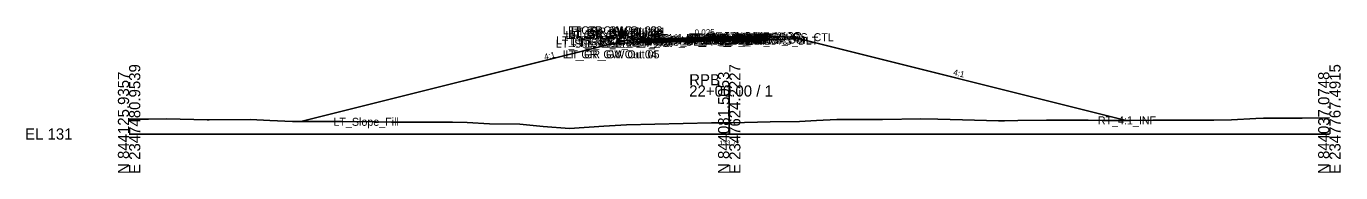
# Model space of a CAD drawing. Extents: x -76 to 2347760, y -10 to 844216.
# Drawn here: x -75.7 to 252.8, y 6990.3 to 7027 of the extents above; entities that cross this region are included whole.
import ezdxf

# ---------------------------------------------------------------- set-up
doc = ezdxf.new("R2010")
doc.units = 0
for name, color, linetype in [('Default', 7, 'Continuous'), ('Exist Cross Section Cell', 7, 'Continuous'), ('Exist XS Center Line Elevation Label', 7, 'Continuous'), ('Exist XS Ground Line', 7, 'Continuous'), ('Prop CMT Pvmt Course 1', 7, 'Continuous'), ('Prop CMT Pvmt Course 2', 7, 'Continuous'), ('Prop CMT Pvmt Course 3', 7, 'Continuous'), ('Prop CMT Pvmt Surface', 7, 'Continuous'), ('Prop CMT Pvmt Surface Shoulder', 7, 'Continuous'), ('Prop CMT Shld Paved Course 1', 7, 'Continuous'), ('Prop CMT Shld Paved Course 2', 7, 'Continuous'), ('Prop CMT Shld Paved Course 3', 7, 'Continuous'), ('Prop CMT Slope Grass', 7, 'Continuous'), ('Prop CMT Subgrade Earthwork', 7, 'Continuous'), ('Prop XS Earthwork Shape', 7, 'Continuous'), ('Prop XS SE Text', 7, 'Continuous'), ('Prop XS Side Slope Text', 7, 'Continuous'), ('Scratch_Level_0', 7, 'Continuous')]:
    doc.layers.add(name, color=color, linetype=linetype)

msp = doc.modelspace()

# ---------------------------------------------------------------- linework, layer by layer
at = {"layer": 'Exist Cross Section Cell'}
for p, q in [((100, 7000), (100, 7012.17)), ((-50, 7000), (100, 7000)), ((100, 7000), (250, 7000))]:
    msp.add_line(p, q, dxfattribs=at)
at = {"layer": 'Exist XS Ground Line'}
msp.add_lwpolyline([(-50, 7003.75), (-45.15, 7003.71), (-40.59, 7003.79), (-30.46, 7003.57), (-29.97, 7003.57), (-19.65, 7003.59), (-14.79, 7003.41), (-9.18, 7003.16), (0.38, 7003.16), (1.29, 7003.15), (3.3, 7003.13), (11.76, 7003.04), (15.56, 7002.99), (19.85, 7002.94), (30.86, 7002.99), (34.5, 7002.88), (40.1, 7002.57), (47.65, 7002.48), (53.53, 7001.9), (60.11, 7001.34), (68.66, 7001.95), (74.34, 7002.33), (95.59, 7002.83), (100, 7002.77), (100.64, 7002.78), (110.23, 7003.03), (117.55, 7003.16), (121.8, 7003.42), (126.93, 7003.6), (136.98, 7003.63), (137.4, 7003.61), (138.35, 7003.63), (147.87, 7003.81), (152.15, 7003.71), (158.34, 7003.53), (167.33, 7003.33), (168.81, 7003.33), (172.11, 7003.38), (179.28, 7003.5), (182.51, 7003.5), (189.75, 7003.46), (193.57, 7003.41), (200.22, 7003.42), (205.87, 7003.46), (210.69, 7003.47), (217.54, 7003.49), (221.16, 7003.48), (225.53, 7003.54), (231.63, 7003.86), (233.53, 7003.99), (239.63, 7003.98), (242.1, 7004), (243.21, 7003.99), (250, 7004.06)], dxfattribs=at)
at = {"layer": 'Prop CMT Pvmt Course 1'}
for p, q in [((100, 7024.31), (88, 7024.01)), ((88, 7023.76), (100, 7024.06)), ((100, 7024.31), (104, 7024.41)), ((100, 7024.06), (100, 7024.31)), ((100, 7024.06), (100, 7024.31)), ((100, 7024.06), (100, 7024.18)), ((100, 7024.18), (100, 7024.18)), ((100, 7024.18), (100, 7024.06)), ((100, 7024.06), (100, 7024.18)), ((100, 7024.18), (100, 7024.18)), ((100, 7024.18), (100, 7024.06)), ((104, 7024.16), (100, 7024.06)), ((100, 7024.06), (100, 7024.06)), ((100, 7024.06), (100, 7024.06)), ((104, 7024.41), (104, 7024.16)), ((88, 7024.01), (88, 7023.76))]:
    msp.add_line(p, q, dxfattribs=at)
at = {"layer": 'Prop CMT Pvmt Course 2'}
for p, q in [((100, 7024.06), (88, 7023.76)), ((100, 7024.06), (104, 7024.16)), ((100, 7023.72), (100, 7024.06)), ((100, 7023.72), (100, 7024.06)), ((104, 7024.16), (104, 7023.82)), ((88, 7023.76), (88, 7023.42)), ((88, 7023.42), (100, 7023.72)), ((104, 7023.82), (100, 7023.72))]:
    msp.add_line(p, q, dxfattribs=at)
at = {"layer": 'Prop CMT Pvmt Course 3'}
for p, q in [((100, 7023.72), (88, 7023.42)), ((88, 7023.42), (88, 7023.09)), ((88, 7023.09), (100, 7023.39)), ((100, 7023.72), (104, 7023.82)), ((100, 7023.39), (100, 7023.72)), ((100, 7023.39), (100, 7023.72)), ((104, 7023.49), (100, 7023.39)), ((104, 7023.82), (104, 7023.49))]:
    msp.add_line(p, q, dxfattribs=at)
at = {"layer": 'Prop CMT Pvmt Surface'}
for q in [(88, 7024.01), (104, 7024.41)]:
    msp.add_line((100, 7024.31), q, dxfattribs=at)
at = {"layer": 'Prop CMT Pvmt Surface Shoulder'}
for p, q in [((104, 7024.41), (108, 7024.51)), ((88, 7024.01), (78, 7023.76))]:
    msp.add_line(p, q, dxfattribs=at)
at = {"layer": 'Prop CMT Shld Paved Course 1'}
for p, q in [((104, 7024.41), (108, 7024.51)), ((104, 7024.16), (104, 7024.41)), ((108.24, 7024.26), (104, 7024.16)), ((108, 7024.51), (108.24, 7024.26)), ((78, 7023.76), (77.74, 7023.5)), ((77.74, 7023.5), (88, 7023.76)), ((88, 7024.01), (78, 7023.76)), ((88, 7023.76), (88, 7024.01))]:
    msp.add_line(p, q, dxfattribs=at)
at = {"layer": 'Prop CMT Shld Paved Course 2'}
for p, q in [((104, 7024.16), (108.24, 7024.26)), ((104, 7023.82), (104, 7024.16)), ((108.24, 7024.26), (108.57, 7023.94)), ((77.74, 7023.5), (77.4, 7023.16)), ((77.4, 7023.16), (88, 7023.42)), ((88, 7023.76), (77.74, 7023.5)), ((88, 7023.42), (88, 7023.76)), ((108.57, 7023.94), (104, 7023.82))]:
    msp.add_line(p, q, dxfattribs=at)
at = {"layer": 'Prop CMT Shld Paved Course 3'}
for p, q in [((76.9, 7023.15), (76.56, 7022.8)), ((76.56, 7022.8), (88, 7023.09)), ((77.4, 7023.16), (76.9, 7023.15)), ((88, 7023.42), (77.4, 7023.16)), ((88, 7023.09), (88, 7023.42)), ((104, 7023.82), (108.57, 7023.94)), ((104, 7023.49), (104, 7023.82)), ((109.39, 7023.62), (104, 7023.49)), ((108.57, 7023.94), (109.07, 7023.95)), ((109.07, 7023.95), (109.39, 7023.62))]:
    msp.add_line(p, q, dxfattribs=at)
at = {"layer": 'Prop CMT Slope Grass'}
for p, q in [((108, 7024.51), (116, 7024.23)), ((116, 7024.23), (199.25, 7003.41)), ((74, 7023.44), (-7.1, 7003.16)), ((78, 7023.76), (74, 7023.44))]:
    msp.add_line(p, q, dxfattribs=at)
at = {"layer": 'Prop CMT Subgrade Earthwork'}
for p, q in [((76.56, 7022.8), (70.9, 7022.66)), ((88, 7023.09), (76.56, 7022.8)), ((100, 7023.39), (88, 7023.09)), ((100, 7023.39), (104, 7023.49)), ((104, 7023.49), (117.59, 7023.83))]:
    msp.add_line(p, q, dxfattribs=at)
at = {"layer": 'Prop XS Earthwork Shape'}
msp.add_lwpolyline([(182.51, 7003.5), (189.75, 7003.46), (193.57, 7003.41), (199.25, 7003.41), (117.59, 7023.83), (104, 7023.49), (100, 7023.39), (88, 7023.09), (76.56, 7022.8), (70.9, 7022.66), (-7.1, 7003.16), (0.38, 7003.16), (1.29, 7003.15), (3.3, 7003.13), (11.76, 7003.04), (15.56, 7002.99), (19.85, 7002.94), (30.86, 7002.99), (34.5, 7002.88), (40.1, 7002.57), (47.65, 7002.48), (53.53, 7001.9), (60.11, 7001.34), (68.66, 7001.95), (74.34, 7002.33), (95.59, 7002.83), (100, 7002.77), (100.64, 7002.78), (110.23, 7003.03), (117.55, 7003.16), (121.8, 7003.42), (126.93, 7003.6), (136.98, 7003.63), (137.4, 7003.61), (138.35, 7003.63), (147.87, 7003.81), (152.15, 7003.71), (158.34, 7003.53), (167.33, 7003.33), (168.81, 7003.33), (172.11, 7003.38), (179.28, 7003.5)], close=True, dxfattribs=at)

# ---------------------------------------------------------------- texts
at = {"layer": 'Default'}
msp.add_text('-', height=0.0001, dxfattribs=at).set_placement((-50, 7000))
at = {"layer": 'Exist Cross Section Cell'}
for s, p in [('N 844125.9357', (-50, 6990)), ('E 2347480.9539', (-47.2, 6990)), ('N 844081.5053', (100, 6990)), ('E 2347624.2227', (102.8, 6990)), ('N 844037.0748', (250, 6990)), ('E 2347767.4915', (252.8, 6990))]:
    msp.add_text(s, height=2.8, rotation=90, dxfattribs=at).set_placement(p)
for s, p in [('RPB', (90, 7012.17)), ('22+00.00 / 1', (90, 7009.37)), ('EL 131', (-76, 6998.6))]:
    msp.add_text(s, height=2.8, dxfattribs=at).set_placement(p)
at = {"layer": 'Exist XS Center Line Elevation Label'}
msp.add_text('133.77', height=1.2, dxfattribs=at).set_placement((97.55, 6997.17))
at = {"layer": 'Prop XS SE Text'}
msp.add_text('0.025', height=1.5, rotation=1.4321, dxfattribs=at).set_placement((91.38, 7024.65))
at = {"layer": 'Prop XS Side Slope Text'}
for rotation, p in [(14.0362, (53.92, 7018.52)), (345.9638, (155.88, 7014.79))]:
    msp.add_text('4:1', height=1.5, rotation=rotation, dxfattribs=at).set_placement(p)
at = {"layer": 'Scratch_Level_0'}
for s, p in [('LT_GS_OS_GR_Face_GW', (56.75, 7022.44)), ('LT_GR_GW Out 03', (58.43, 7024.94)), ('LT_GR_GW Out 06', (59.05, 7023.77)), ('LT_GR_GW Out 02', (59.77, 7024.94)), ('LT_GR_GW Out 09', (59.77, 7024.35)), ('LT_GR_GW Out 07', (59.77, 7023.77)), ('LT_GR_GW Out 08', (60.04, 7024.06)), ('LT_GS_OS_CTL', (60.36, 7022.2)), ('LT_GR_GW Out 01', (60.6, 7024.64)), ('LT_PS3_Shelf_Out', (62.89, 7022.15)), ('LT_PS3_OEOP', (67.64, 7022.16)), ('LT_PS2_OEOP', (67.98, 7022.5)), ('LT_PS1_OEOP', (68.8, 7022.76)), ('LT_Sub_OEOT', (78.08, 7022.09)), ('LT_PV2_OEOT', (78.17, 7022.76)), ('LT_PV3_OEOT', (78.17, 7022.42)), ('LT_PV1_OEOT', (78.74, 7023.01)), ('RT_Sub_OEEOP', (89.17, 7022.39)), ('LT_Sub_OEEOP', (89.21, 7022.39)), ('RT_PV2_OEEOP', (89.26, 7023.06)), ('RT_PV3_OEEOP', (89.26, 7022.72)), ('LT_PV2_OEEOP', (89.31, 7023.06)), ('LT_PV3_OEEOP', (89.31, 7022.72)), ('RT_PV1_OEEOP', (89.83, 7023.18)), ('LT_PV1_OEEOP', (89.87, 7023.18)), ('RT_PV2_IEEOP', (89.91, 7023.06)), ('LT_PV2_IEEOP', (89.95, 7023.06)), ('RT_PV1_IEEOP', (90.47, 7023.18)), ('LT_PV1_IEEOP', (90.52, 7023.18)), ('RT_Sub_Trench_Out', (93.55, 7022.62)), ('PV2_PGL', (93.91, 7023.06)), ('RT_Sub_OEOT', (94.03, 7022.49)), ('RT_PV2_OEOT', (94.13, 7023.16)), ('RT_PV3_OEOT', (94.13, 7022.82)), ('PV1_PGL', (94.47, 7023.31)), ('RT_PV1_OEOT', (94.69, 7023.41)), ('RT_PS3_Shelf_Out', (95.01, 7022.95)), ('RT_PS2_OEOP', (98.43, 7023.26)), ('RT_Sub_OSS_DLT', (98.75, 7022.36)), ('RT_PS1_OEOP', (98.76, 7023.51)), ('RT_PS3_OEOP', (98.76, 7022.94)), ('RT_GS_OS_CTL', (105.32, 7023.23)), ('LT_Sub_OSS_DLT', (56.67, 7021.62)), ('LT_GR_GW Out 04', (58.43, 7018.94)), ('LT_GR_GW Out 05', (59.1, 7018.94)), ('LT_Sub_Trench_Out', (60.76, 7021.8)), ('RT_4:1_INF', (192.13, 7002.41)), ('LT_Slope_Fill', (1.08, 7002.05))]:
    msp.add_text(s, height=2, dxfattribs=at).set_placement(p)

doc.saveas('drawing.dxf')
